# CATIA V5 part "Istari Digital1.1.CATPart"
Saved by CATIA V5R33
Part number: Istari Digital1.1
Property "V_IsManufacturable": "true"
Property "V_Scale": "NormalScale"
Property "V_isTerminal": "true"
Property "V_ChangeHistory": "false"
Property "V_isLastVersion": "true"
Property "V_isVPLMControlled": "true"
Property "V_AuthorityControl": "false"
Property "V_ProjectApplicability": "List"
Property "V_Name": "Istari Digital"
Property "PLM_ExternalID": "prd00000090"
Property "V_usage": "3DPart"
Property "V_nature": "Definition"
Property "V_sec_level": "-1"
Property "owner": "admin_platform"
Property "project": "New Space 1"
Property "organization": "Company Name"
Property "revision": "1.1"
Property "originated": "03/11/2024 :: 05:01:32 PM"
Property "modified": "03/11/2024 :: 05:07:02 PM"
Property "reserved": "true"
Property "reservedby": "admin_platform"
Property "current": "IN_WORK"
Property "name": "prd00000090"
Property "locked": "false"
Property "revindex": "0"
Property "isbestsofar": "true"
Property "minorrevision": "1"
Property "majorrevision": "1"
Property "ispublished": "false"
Property "policy": "VPLM_SMB_Definition"
Bounding box of the stored display mesh (mm): x -20 to 0, y 2.426 to 200.653, z -7.468 to 25.4
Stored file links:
  C:\Users\Chris Brodowski\Documents\3D Objects\Export\Istari Digital1.1.CATPart

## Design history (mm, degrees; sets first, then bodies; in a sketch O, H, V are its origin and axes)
Parameters
  `Letter Depth` = 20 mm
  `Letter Height` = 25.4 mm
MechanicalRefPlane1 "xy-plane"
MechanicalRefPlane2 "yz-plane"
MechanicalRefPlane3 "zx-plane"
AxisSystem1: origin (0, 0, 0), X (1, 0, 0), Y (0, 1, 0), Z (0, 0, 1)
Body1 (main body)
  Sketch1 "Text_SKETCH" on MechanicalRefPlane2, origin (0, 0, 0), H (0, 1, 0), V (0, 0, 1)
    curve C1
  Pad1: profile Sketch1, direction (-1, 0, 0), length 20 {= `Letter Depth`}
